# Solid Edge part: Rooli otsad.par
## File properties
Author: KULL
Template: Iso Metric Part.par
Last saved by: KULL
Revision: 6
Application: Solid Edge
Accuracy: 0,990
Face Style: Model Default
Fill Style: Normal
Coef. of Thermal Exp: 0.0
Thermal Conductivity: 0.0
Specific Heat: 0.0
Modulus of Elasticity: 0.0
Poisson's Ratio: 0.0
Yield Stress: 0.0
Ultimate Stress: 0.0
Elongation: 0.0
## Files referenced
..\..\Rover_ASM.asm
D:\Solid edge leong\Solid edge Sync practice\ROVER_Heiko_Kull_EKSAM\Roolimise_jupid\frontsteering_1.par
D:\Solid edge leong\Solid edge Sync practice\ROVER_Heiko_Kull_EKSAM\Roolimise_jupid\Roolivõimu silindri varras.par
imu silindri varras.par
QD:\Solid edge leong\Solid edge Sync practice\ROVER_Heiko_Kull_EKSAM\Rover_ASM.asm
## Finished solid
Body 1: sheet body, 1 face, 22 edges, 22 vertices.
  Faces by surface: plane 1
  Edges by curve: circle 12, intersection 4, line 4, ellipse 2
Body 2: solid body, 12 faces, 11 edges, 0 vertices.
  Faces by surface: torus 5, sphere 4, cylinder 3
  Edges by curve: circle 11
Body 3: sheet body, 1 face, 1 edge, 0 vertices.
  Faces by surface: sphere 1
  Edges by curve: circle 1
Body 4: sheet body, 1 face, 1 edge, 0 vertices.
  Faces by surface: sphere 1
  Edges by curve: circle 1
Bounding box of the edges (mm; curved faces can reach further): 6.889 x 50.856 x 15.444, from (-25.2222, 57.4669, 16.8206) to (-18.3328, 108.3233, 32.2645).
Cylindrical faces by radius (mm): R1.5 x1, R2 x1, R2.5 x1
Toroidal faces (ring radius, tube radius in mm): R2.3 r0.3 x1, R2.4 r0.4 x1, R2.9 r0.4 x1, R3.5 r2 x2
Spherical faces by radius (mm): R2.5 x1, R3 x3, R4 x2
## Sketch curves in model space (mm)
line (-22, 104.3891, 28.2645) -> (-22, 60, 20.8206)
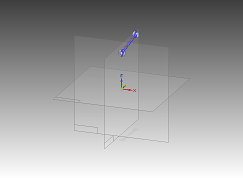
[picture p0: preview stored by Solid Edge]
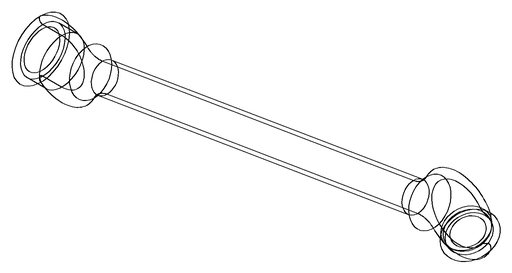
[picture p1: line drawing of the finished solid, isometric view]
